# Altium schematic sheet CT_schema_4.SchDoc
size 368 x 245 mm
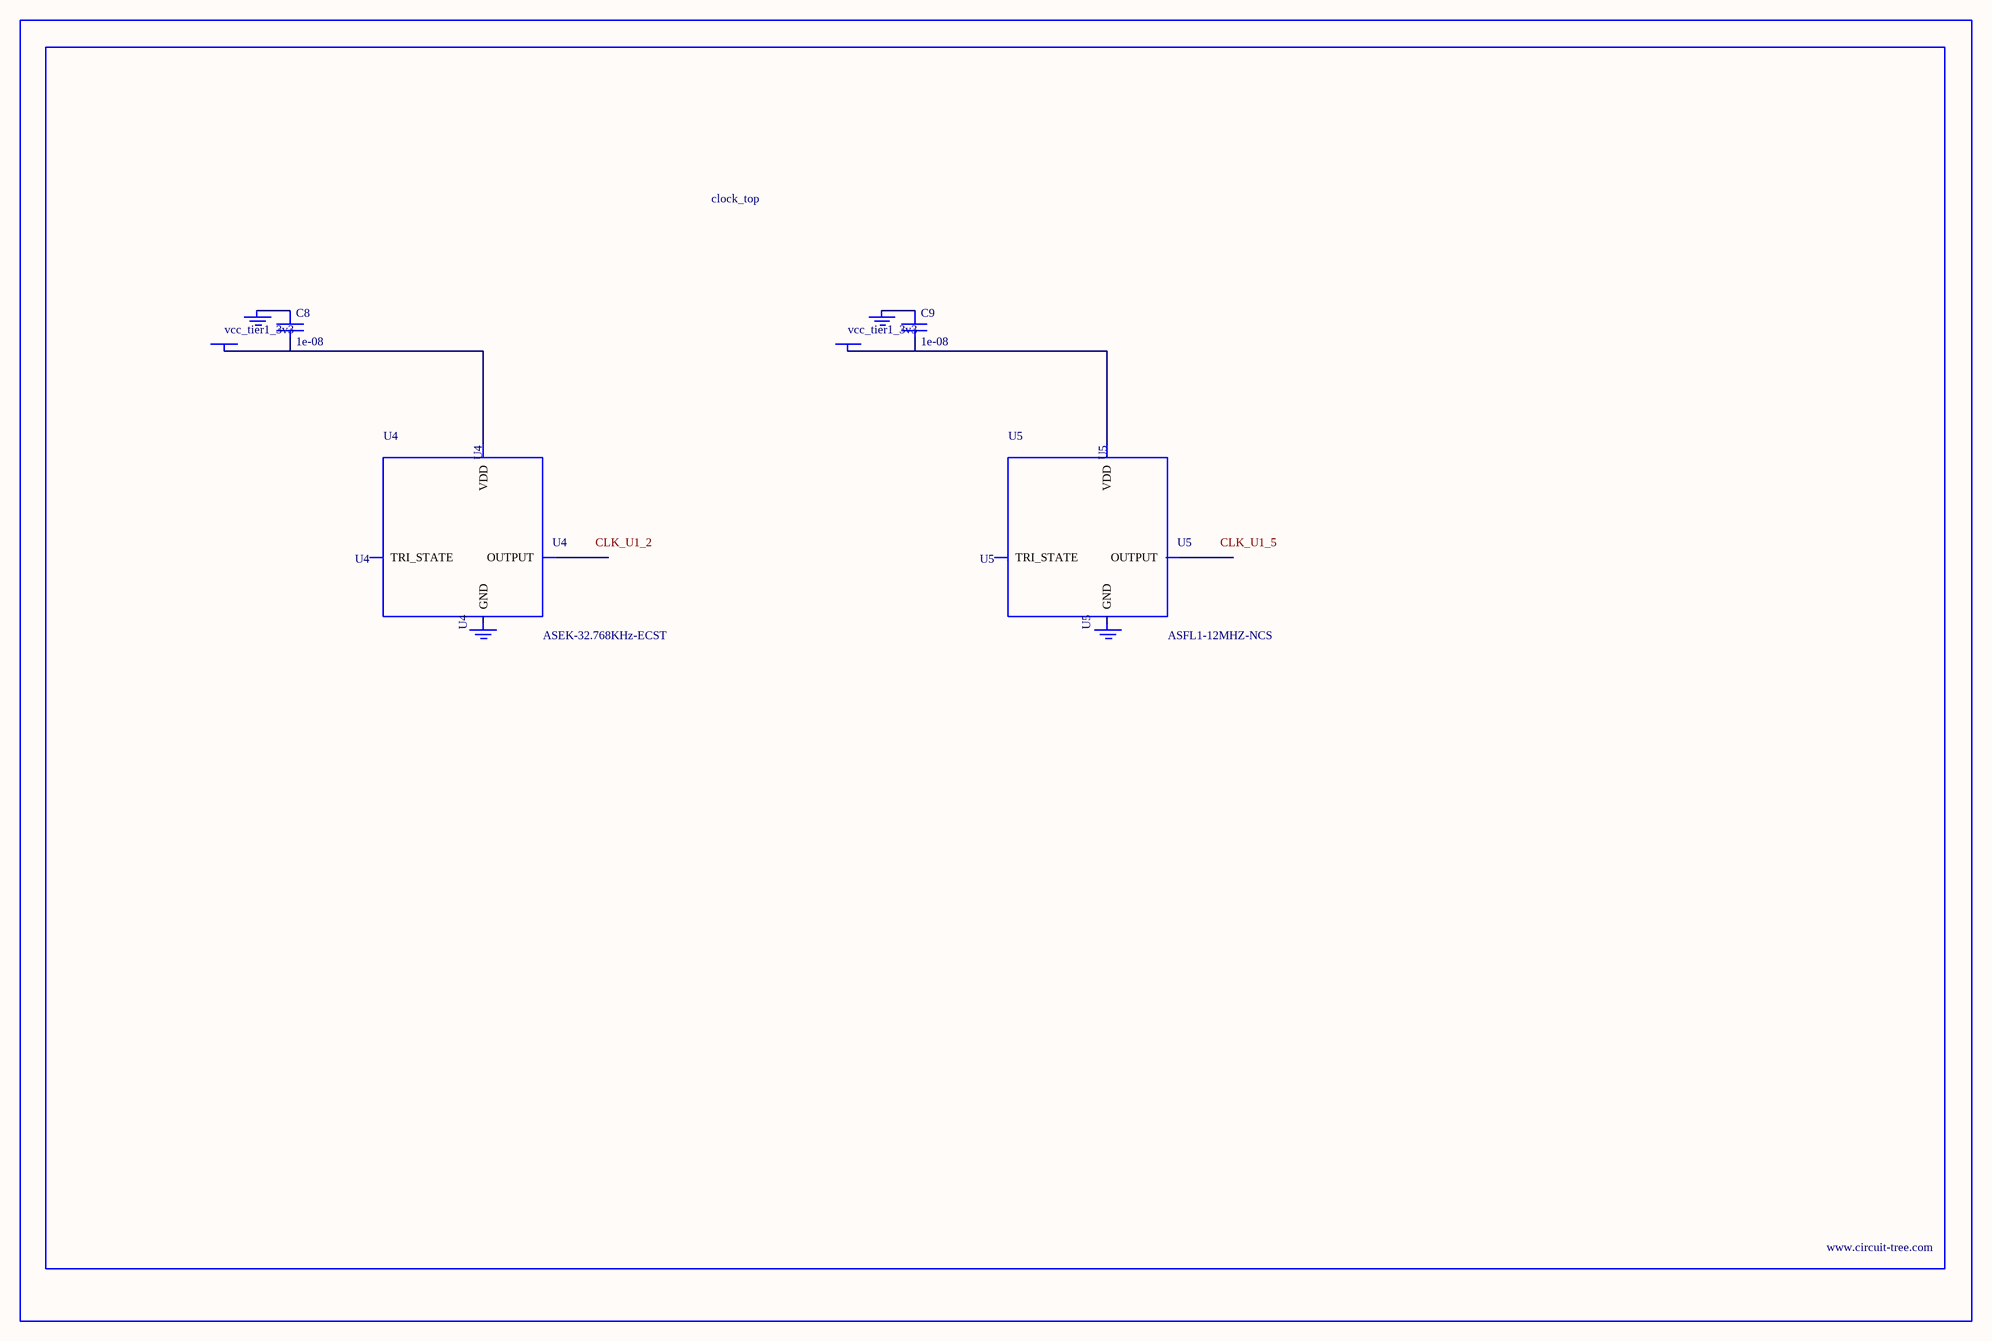
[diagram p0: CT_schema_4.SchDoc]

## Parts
BORDER3  (no value)
C8  1e-08  [C0402]
C9  1e-08  [C0402]
GND_INSTANCE_3_0  (no value)
GND_INSTANCE_3_1  (no value)
GND_INSTANCE_3_2  (no value)
GND_INSTANCE_3_3  (no value)
POWER_INSTANCE_3_0  vcc_tier1_3v3
POWER_INSTANCE_3_1  vcc_tier1_3v3
U4  ASEK-32.768KHz-ECST  [ASEK]
U5  ASFL1-12MHZ-NCS  [ASFL1]

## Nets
NetC8_1: C8.1 GND_INSTANCE_3_0.0(GND)
NetC8_2: C8.2 POWER_INSTANCE_3_0.0(PWR) U4.4(VDD)
NetC9_1: C9.1 GND_INSTANCE_3_2.0(GND)
NetC9_2: C9.2 POWER_INSTANCE_3_1.0(PWR) U5.4(VDD)

Not connected (* = marked no-connect by the designer): GND_INSTANCE_3_1 0(GND); GND_INSTANCE_3_3 0(GND); U4 1(TRI_STATE) 2(GND) 3(OUTPUT); U5 1(TRI_STATE) 2(GND) 3(OUTPUT)

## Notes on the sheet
- Labels drawn without touching a wire or pin: CLK_U1_2, CLK_U1_5

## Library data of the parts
BORDER3 = BORDER_PAGE3
C8 C9 = C0402C103K3RAC
GND_INSTANCE_3_0-GND_INSTANCE_3_3 = GND
POWER_INSTANCE_3_0 POWER_INSTANCE_3_1 = PWR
